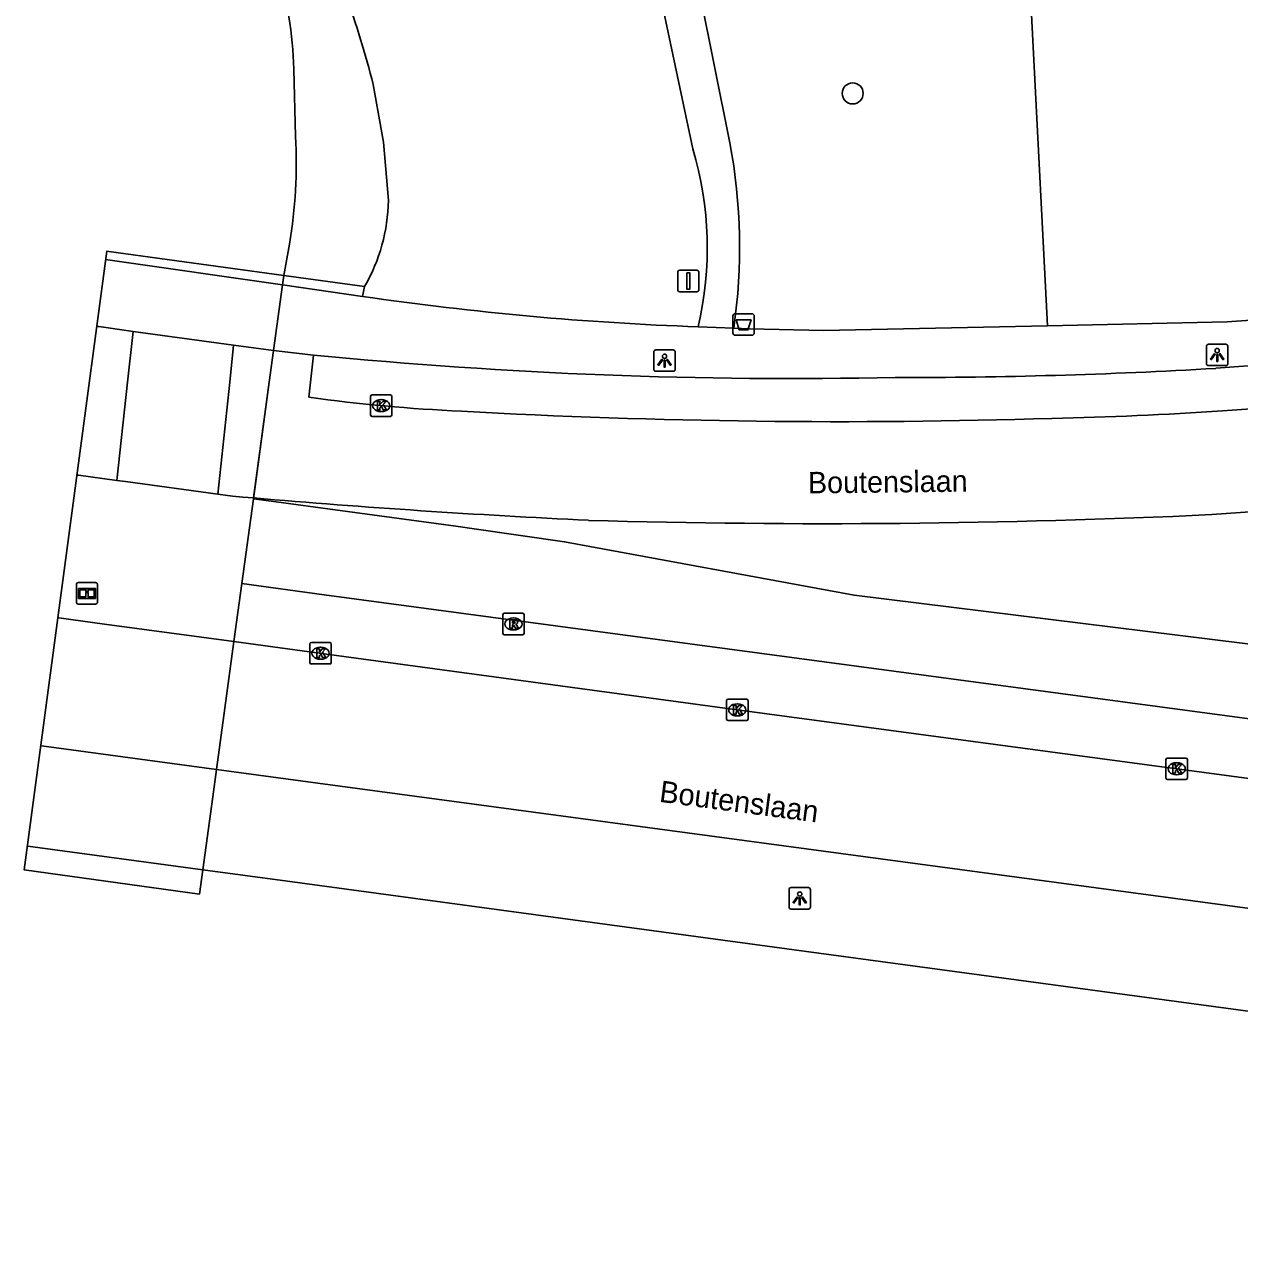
# Model space of a CAD drawing. Extents: x 161141 to 161601, y 381708 to 382245.
# Drawn here: x 161258.8 to 161315.4, y 381710.1 to 381766.7 of the extents above; entities that cross this region are included whole.
import ezdxf

# ---------------------------------------------------------------- set-up
doc = ezdxf.new("R2010")
doc.units = 0
for name, color, linetype in [('IMGEO_Afvalbak', 7, 'Continuous'), ('IMGEO_Berm_groen', 7, 'Continuous'), ('IMGEO_Boom', 7, 'Continuous'), ('IMGEO_Dek', 7, 'Continuous'), ('IMGEO_Informatiebord', 7, 'Continuous'), ('IMGEO_Kolk', 7, 'Continuous'), ('IMGEO_Lichtpunt', 7, 'Continuous'), ('IMGEO_Loofbos', 7, 'Continuous'), ('IMGEO_Muur', 7, 'Continuous'), ('IMGEO_Openbare_ruimte_label', 7, 'Continuous'), ('IMGEO_Rijbaan_lokaal_open', 7, 'Continuous'), ('IMGEO_Rijbaan_regionaal_gesloten', 7, 'Continuous'), ('IMGEO_Rioolput', 7, 'Continuous'), ('IMGEO_Verkeersbordpaal', 7, 'Continuous'), ('IMGEO_Voetpad_halfverhard', 7, 'Continuous'), ('IMGEO_Voetpad_open', 7, 'Continuous'), ('IMGEO_Waterloop', 7, 'Continuous')]:
    doc.layers.add(name, color=color, linetype=linetype)

msp = doc.modelspace()

# ---------------------------------------------------------------- linework, layer by layer
at = {"layer": 'IMGEO_Afvalbak'}
for p, q in [((161291.928, 381753.192), (161292.718, 381753.192)), ((161292.718, 381753.192), (161291.928, 381753.192)), ((161291.828, 381752.292), (161291.828, 381753.092)), ((161291.828, 381753.092), (161291.828, 381752.292)), ((161292.818, 381753.092), (161292.818, 381752.292)), ((161292.818, 381752.292), (161292.818, 381753.092)), ((161292.718, 381752.192), (161291.928, 381752.192)), ((161291.928, 381752.192), (161292.718, 381752.192))]:
    msp.add_line(p, q, dxfattribs=at)
msp.add_lwpolyline([(161291.971, 381752.906), (161292.675, 381752.906), (161292.526, 381752.436), (161292.12, 381752.436), (161291.971, 381752.906)], dxfattribs=at)
for centre, start, end in [((161291.928, 381753.092), 90, 180), ((161291.928, 381753.092), 90, 180), ((161292.718, 381753.092), 0, 90), ((161292.718, 381753.092), 360, 90), ((161291.928, 381752.292), 180, 270), ((161291.928, 381752.292), 180, 270), ((161292.718, 381752.292), 270, 0), ((161292.718, 381752.292), 270, 0)]:
    msp.add_arc(centre, 0.1, start, end, dxfattribs=at)
at = {"layer": 'IMGEO_Berm_groen'}
for points in [[(161397.032, 381723.44), (161397.056, 381723.621), (161396.92, 381724.62), (161396.612, 381725.505), (161395.912, 381726.127), (161393.777, 381727.484), (161392.598, 381727.943), (161386.682, 381728.916), (161372.991, 381730.97), (161355.514, 381733.064), (161324.679, 381736.724), (161297.467, 381740.089), (161283.989, 381742.578), (161279.785, 381743.184), (161278.93, 381743.302), (161273.313, 381744.063), (161270.564, 381744.435), (161269.503, 381744.577)], [(161268.964, 381740.632), (161272.807, 381740.117), (161390.902, 381724.29), (161397.032, 381723.44)]]:
    msp.add_lwpolyline(points, dxfattribs=at)
at = {"layer": 'IMGEO_Boom'}
msp.add_circle((161297.402, 381763.444), 0.489, dxfattribs=at)
at = {"layer": 'IMGEO_Dek'}
msp.add_lwpolyline([(161266.992, 381726.19), (161267.146, 381727.315), (161267.61, 381730.715), (161267.783, 381731.983), (161268.174, 381734.839), (161268.596, 381737.935), (161268.964, 381740.632), (161269.503, 381744.577), (161270.244, 381750), (161270.446, 381751.48), (161270.863, 381754.533), (161270.924, 381754.975), (161262.781, 381756.092), (161262.685, 381756.105), (161258.842, 381727.311)], close=True, dxfattribs=at)
at = {"layer": 'IMGEO_Informatiebord'}
for p, q in [((161261.264, 381739.778), (161261.264, 381740.578)), ((161261.264, 381740.578), (161261.264, 381739.778)), ((161261.364, 381740.678), (161262.154, 381740.678)), ((161262.154, 381740.678), (161261.364, 381740.678)), ((161262.254, 381740.578), (161262.254, 381739.778)), ((161262.254, 381739.778), (161262.254, 381740.578)), ((161262.154, 381739.678), (161261.364, 381739.678)), ((161261.364, 381739.678), (161262.154, 381739.678))]:
    msp.add_line(p, q, dxfattribs=at)
for points in [[(161261.365, 381740.41), (161262.153, 381740.41), (161262.153, 381739.946), (161261.365, 381739.946), (161261.365, 381740.41)], [(161261.43, 381740.345), (161261.43, 381740.011), (161261.705, 381740.011), (161261.706, 381740.224), (161261.81, 381740.225), (161261.811, 381740.011), (161262.088, 381740.011), (161262.088, 381740.345), (161261.812, 381740.345), (161261.812, 381740.265), (161261.706, 381740.265), (161261.706, 381740.345), (161261.43, 381740.345)]]:
    msp.add_lwpolyline(points, dxfattribs=at)
for centre, start, end in [((161261.364, 381740.578), 90, 180), ((161261.364, 381740.578), 90, 180), ((161262.154, 381740.578), 0, 90), ((161262.154, 381740.578), 360, 90), ((161261.364, 381739.778), 180, 270), ((161261.364, 381739.778), 180, 270), ((161262.154, 381739.778), 270, 0), ((161262.154, 381739.778), 270, 0)]:
    msp.add_arc(centre, 0.1, start, end, dxfattribs=at)
at = {"layer": 'IMGEO_Kolk'}
for p, q in [((161274.954, 381748.489), (161274.954, 381749.341)), ((161275.029, 381749.415), (161275.881, 381749.415)), ((161275.955, 381749.341), (161275.955, 381748.489)), ((161275.442, 381749.195), (161275.467, 381749.195)), ((161275.881, 381748.415), (161275.029, 381748.415)), ((161275.465, 381748.635), (161275.44, 381748.635)), ((161272.131, 381736.967), (161272.131, 381737.819)), ((161272.206, 381737.893), (161273.058, 381737.893)), ((161272.619, 381737.673), (161272.644, 381737.673)), ((161273.132, 381737.819), (161273.132, 381736.967)), ((161273.058, 381736.893), (161272.206, 381736.893)), ((161272.642, 381737.113), (161272.617, 381737.113)), ((161291.53, 381734.332), (161291.53, 381735.184)), ((161291.605, 381735.258), (161292.457, 381735.258)), ((161292.531, 381735.184), (161292.531, 381734.332)), ((161292.018, 381735.038), (161292.043, 381735.038)), ((161292.457, 381734.258), (161291.605, 381734.258)), ((161292.041, 381734.478), (161292.016, 381734.478)), ((161311.983, 381731.591), (161311.983, 381732.443)), ((161312.058, 381732.517), (161312.91, 381732.517)), ((161312.471, 381732.297), (161312.496, 381732.297)), ((161312.984, 381732.443), (161312.984, 381731.591)), ((161312.494, 381731.737), (161312.469, 381731.737)), ((161312.91, 381731.517), (161312.058, 381731.517))]:
    msp.add_line(p, q, dxfattribs=at)
for points in [[(161274.954, 381748.489), (161274.954, 381749.341)], [(161275.029, 381749.415), (161275.881, 381749.415)], [(161275.955, 381749.341), (161275.955, 381748.489)], [(161275.275, 381749.115), (161275.398, 381749.115), (161275.398, 381748.964), (161275.528, 381749.115), (161275.692, 381749.115), (161275.546, 381748.964), (161275.699, 381748.715), (161275.547, 381748.715), (161275.462, 381748.879), (161275.398, 381748.812), (161275.398, 381748.715), (161275.275, 381748.715), (161275.275, 381749.115)], [(161275.881, 381748.415), (161275.029, 381748.415)], [(161272.131, 381736.967), (161272.131, 381737.819)], [(161272.206, 381737.893), (161273.058, 381737.893)], [(161272.452, 381737.593), (161272.575, 381737.593), (161272.575, 381737.442), (161272.705, 381737.593), (161272.869, 381737.593), (161272.723, 381737.442), (161272.876, 381737.193), (161272.724, 381737.193), (161272.639, 381737.357), (161272.575, 381737.29), (161272.575, 381737.193), (161272.452, 381737.193), (161272.452, 381737.593)], [(161273.132, 381737.819), (161273.132, 381736.967)], [(161273.058, 381736.893), (161272.206, 381736.893)], [(161291.53, 381734.332), (161291.53, 381735.184)], [(161291.605, 381735.258), (161292.457, 381735.258)], [(161292.531, 381735.184), (161292.531, 381734.332)], [(161291.851, 381734.958), (161291.974, 381734.958), (161291.974, 381734.807), (161292.104, 381734.958), (161292.268, 381734.958), (161292.122, 381734.807), (161292.275, 381734.558), (161292.123, 381734.558), (161292.038, 381734.722), (161291.974, 381734.655), (161291.974, 381734.558), (161291.851, 381734.558), (161291.851, 381734.958)], [(161292.457, 381734.258), (161291.605, 381734.258)], [(161311.983, 381731.591), (161311.983, 381732.443)], [(161312.058, 381732.517), (161312.91, 381732.517)], [(161312.984, 381732.443), (161312.984, 381731.591)], [(161312.304, 381732.217), (161312.427, 381732.217), (161312.427, 381732.066), (161312.557, 381732.217), (161312.721, 381732.217), (161312.575, 381732.066), (161312.728, 381731.817), (161312.576, 381731.817), (161312.491, 381731.981), (161312.427, 381731.914), (161312.427, 381731.817), (161312.304, 381731.817), (161312.304, 381732.217)], [(161312.91, 381731.517), (161312.058, 381731.517)]]:
    msp.add_lwpolyline(points, dxfattribs=at)
for centre, start, end in [((161275.031, 381749.339), 91.552, 178.448), ((161275.031, 381749.339), 91.552, 178.448), ((161275.879, 381749.339), 1.552, 88.448), ((161275.879, 381749.339), 1.552, 88.448), ((161275.031, 381748.491), 181.552, 268.448), ((161275.031, 381748.491), 181.552, 268.448), ((161275.879, 381748.491), 271.552, 358.448), ((161275.879, 381748.491), 271.552, 358.448), ((161272.208, 381737.817), 91.552, 178.448), ((161272.208, 381737.817), 91.552, 178.448), ((161273.056, 381737.817), 1.552, 88.448), ((161273.056, 381737.817), 1.552, 88.448), ((161272.208, 381736.969), 181.552, 268.448), ((161272.208, 381736.969), 181.552, 268.448), ((161273.056, 381736.969), 271.552, 358.448), ((161273.056, 381736.969), 271.552, 358.448), ((161291.607, 381735.182), 91.552, 178.448), ((161291.607, 381735.182), 91.552, 178.448), ((161292.455, 381735.182), 1.552, 88.448), ((161292.455, 381735.182), 1.552, 88.448), ((161291.607, 381734.334), 181.552, 268.448), ((161291.607, 381734.334), 181.552, 268.448), ((161292.455, 381734.334), 271.552, 358.448), ((161292.455, 381734.334), 271.552, 358.448), ((161312.06, 381732.441), 91.552, 178.448), ((161312.06, 381732.441), 91.552, 178.448), ((161312.908, 381732.441), 1.552, 88.448), ((161312.908, 381732.441), 1.552, 88.448), ((161312.06, 381731.593), 181.552, 268.448), ((161312.06, 381731.593), 181.552, 268.448), ((161312.908, 381731.593), 271.552, 358.448), ((161312.908, 381731.593), 271.552, 358.448)]:
    msp.add_arc(centre, 0.0765, start, end, dxfattribs=at)
for centre, major_axis, ratio, start_param, end_param in [((161275.441, 381748.915), (-0.387, 0.002), 0.722429, 4.712389, 7.853982), ((161275.466, 381748.915), (-0.39, 0.002), 0.717154, 1.570796, 4.712389), ((161272.618, 381737.393), (-0.387, 0.002), 0.722429, 4.712389, 7.853982), ((161272.643, 381737.393), (-0.39, 0.002), 0.717154, 1.570796, 4.712389), ((161292.017, 381734.758), (-0.387, 0.002), 0.722429, 4.712389, 7.853982), ((161292.042, 381734.758), (-0.39, 0.002), 0.717154, 1.570796, 4.712389), ((161312.47, 381732.017), (-0.387, 0.002), 0.722429, 4.712389, 7.853982), ((161312.495, 381732.017), (-0.39, 0.002), 0.717154, 1.570796, 4.712389)]:
    msp.add_ellipse(centre, major_axis=major_axis, ratio=ratio, start_param=start_param, end_param=end_param, dxfattribs=at)
at = {"layer": 'IMGEO_Lichtpunt'}
for p, q in [((161289.046, 381751.508), (161288.238, 381751.508)), ((161289.046, 381751.508), (161288.238, 381751.508)), ((161313.869, 381751.677), (161313.869, 381750.87)), ((161313.869, 381751.677), (161313.869, 381750.87)), ((161314.771, 381751.772), (161313.963, 381751.772)), ((161314.771, 381751.772), (161313.963, 381751.772)), ((161314.865, 381750.87), (161314.865, 381751.677)), ((161314.865, 381750.87), (161314.865, 381751.677)), ((161288.144, 381751.413), (161288.144, 381750.606)), ((161288.144, 381751.413), (161288.144, 381750.606)), ((161289.14, 381750.606), (161289.14, 381751.413)), ((161289.14, 381750.606), (161289.14, 381751.413)), ((161288.238, 381750.512), (161289.046, 381750.512)), ((161288.238, 381750.512), (161289.046, 381750.512)), ((161313.963, 381750.776), (161314.771, 381750.776)), ((161313.963, 381750.776), (161314.771, 381750.776)), ((161294.439, 381726.392), (161294.439, 381725.585)), ((161294.439, 381726.392), (161294.439, 381725.585)), ((161295.341, 381726.487), (161294.533, 381726.487)), ((161295.341, 381726.487), (161294.533, 381726.487)), ((161295.435, 381725.585), (161295.435, 381726.392)), ((161295.435, 381725.585), (161295.435, 381726.392)), ((161294.533, 381725.491), (161295.341, 381725.491)), ((161294.533, 381725.491), (161295.341, 381725.491))]:
    msp.add_line(p, q, dxfattribs=at)
for points in [[(161288.518, 381751.077), (161288.557, 381751.049), (161288.369, 381750.787), (161288.331, 381750.814), (161288.518, 381751.077)], [(161288.62, 381751.029), (161288.667, 381751.029), (161288.667, 381750.707), (161288.62, 381750.707), (161288.62, 381751.029)], [(161288.73, 381751.049), (161288.768, 381751.076), (161288.955, 381750.814), (161288.916, 381750.786), (161288.73, 381751.049)], [(161314.243, 381751.341), (161314.282, 381751.313), (161314.094, 381751.051), (161314.056, 381751.078), (161314.243, 381751.341)], [(161314.345, 381751.293), (161314.392, 381751.293), (161314.392, 381750.971), (161314.345, 381750.971), (161314.345, 381751.293)], [(161314.455, 381751.313), (161314.493, 381751.34), (161314.68, 381751.078), (161314.641, 381751.05), (161314.455, 381751.313)], [(161294.813, 381726.056), (161294.852, 381726.028), (161294.664, 381725.766), (161294.626, 381725.793), (161294.813, 381726.056)], [(161295.025, 381726.028), (161295.063, 381726.055), (161295.25, 381725.793), (161295.211, 381725.765), (161295.025, 381726.028)], [(161294.915, 381726.008), (161294.962, 381726.008), (161294.962, 381725.686), (161294.915, 381725.686), (161294.915, 381726.008)]]:
    msp.add_lwpolyline(points, dxfattribs=at)
for centre in [(161314.368, 381751.475), (161288.643, 381751.211), (161294.938, 381726.19)]:
    msp.add_circle(centre, 0.0994, dxfattribs=at)
for centre, start, end in [((161288.238, 381751.413), 90, 180), ((161288.238, 381751.413), 90, 180), ((161289.046, 381751.413), 0, 90), ((161289.046, 381751.413), 0, 90), ((161313.963, 381751.677), 90, 180), ((161313.963, 381751.677), 90, 180), ((161314.771, 381751.677), 0, 90), ((161314.771, 381751.677), 0, 90), ((161288.238, 381750.606), 180, 270), ((161288.238, 381750.606), 180, 270), ((161289.046, 381750.606), 270, 0), ((161289.046, 381750.606), 270, 360), ((161313.963, 381750.87), 180, 270), ((161313.963, 381750.87), 180, 270), ((161314.771, 381750.87), 270, 0), ((161314.771, 381750.87), 270, 360), ((161294.533, 381726.392), 90, 180), ((161294.533, 381726.392), 90, 180), ((161295.341, 381726.392), 0, 90), ((161295.341, 381726.392), 0, 90), ((161294.533, 381725.585), 180, 270), ((161294.533, 381725.585), 180, 270), ((161295.341, 381725.585), 270, 0), ((161295.341, 381725.585), 270, 360)]:
    msp.add_arc(centre, 0.0946, start, end, dxfattribs=at)
at = {"layer": 'IMGEO_Loofbos'}
for points in [[(161306.475, 381752.633), (161304.865, 381783.723)], [(161275.788, 381758.457), (161275.561, 381761.176), (161275.087, 381763.862)]]:
    msp.add_lwpolyline(points, dxfattribs=at)
for centre, radius, start, end in [((161225.5, 381750.991), 51.23, 14.5512, 24.2931), ((161267.538, 381758.589), 8.251, 329.9766, 359.0817)]:
    msp.add_arc(centre, radius, start, end, dxfattribs=at)
at = {"layer": 'IMGEO_Muur'}
for points in [[(161270.863, 381754.533), (161262.727, 381755.697), (161262.632, 381755.711)], [(161270.863, 381754.533), (161270.924, 381754.975)], [(161270.924, 381754.975), (161274.682, 381754.461)], [(161274.587, 381754), (161270.863, 381754.533)], [(161274.682, 381754.461), (161274.587, 381754)]]:
    msp.add_lwpolyline(points, dxfattribs=at)
at = {"layer": 'IMGEO_Rijbaan_lokaal_open'}
for points in [[(161262.217, 381752.605), (161262.303, 381752.593), (161262.639, 381752.544), (161263.907, 381752.371)], [(161263.146, 381745.438), (161263.647, 381750), (161263.907, 381752.371)], [(161263.907, 381752.371), (161268.584, 381751.734)], [(161268.584, 381751.734), (161268.402, 381750), (161267.855, 381744.799)], [(161268.584, 381751.734), (161270.446, 381751.48)], [(161269.509, 381744.62), (161270.244, 381750), (161270.446, 381751.48)], [(161269.509, 381744.62), (161270.244, 381750), (161270.446, 381751.48)], [(161272.307, 381751.27), (161270.446, 381751.48)], [(161272.307, 381751.27), (161272.086, 381749.309)], [(161314.611, 381748.68), (161328.834, 381749.672)], [(161263.146, 381745.438), (161261.357, 381745.672), (161261.293, 381745.681)], [(161267.855, 381744.799), (161263.559, 381745.382), (161263.146, 381745.438)], [(161269.509, 381744.62), (161269.019, 381744.662), (161268.53, 381744.705), (161267.855, 381744.799)], [(161314.112, 381743.844), (161329.226, 381744.898)]]:
    msp.add_lwpolyline(points, dxfattribs=at)
for centre, radius, start, end in [((161282.514, 381823.873), 75.289, 262.03887, 267.46603), ((161303.629, 381903.982), 155.69, 271.12049, 274.04469), ((161296.792, 382065.432), 317.264, 266.81866, 271.78491), ((161305.423, 382165.044), 421.955, 265.11741, 267.24079), ((161296.089, 382127.744), 384.323, 268.36314, 272.68788)]:
    msp.add_arc(centre, radius, start, end, dxfattribs=at)
at = {"layer": 'IMGEO_Rijbaan_regionaal_gesloten'}
for points in [[(161260.408, 381739.045), (161260.451, 381739.039), (161262.58, 381738.75), (161268.596, 381737.935)], [(161267.783, 381731.983), (161268.174, 381734.839), (161268.596, 381737.935)], [(161268.596, 381737.935), (161272.46, 381737.411), (161292.031, 381734.758), (161396.904, 381720.692)], [(161267.783, 381731.983), (161259.637, 381733.078), (161259.612, 381733.081)], [(161396.075, 381714.735), (161271.697, 381731.457), (161267.783, 381731.983)], [(161258.99, 381728.417), (161259, 381728.416), (161267.146, 381727.315)], [(161266.992, 381726.19), (161267.146, 381727.315)], [(161395.417, 381710.059), (161388.748, 381710.952), (161341.985, 381717.206), (161295.256, 381723.516), (161271.097, 381726.781), (161267.146, 381727.315)]]:
    msp.add_lwpolyline(points, dxfattribs=at)
at = {"layer": 'IMGEO_Rioolput'}
for p, q in [((161281.11, 381738.33), (161281.11, 381739.182)), ((161281.185, 381739.256), (161282.037, 381739.256)), ((161282.111, 381739.182), (161282.111, 381738.33)), ((161281.621, 381738.476), (161281.596, 381738.476)), ((161281.598, 381739.036), (161281.623, 381739.036)), ((161282.037, 381738.256), (161281.185, 381738.256))]:
    msp.add_line(p, q, dxfattribs=at)
for points in [[(161281.11, 381738.33), (161281.11, 381739.182)], [(161281.185, 381739.256), (161282.037, 381739.256)], [(161282.111, 381739.182), (161282.111, 381738.33)], [(161281.699, 381738.954), (161281.447, 381738.956), (161281.447, 381738.556)], [(161281.447, 381738.556), (161281.571, 381738.556), (161281.571, 381738.718), (161281.582, 381738.718)], [(161281.625, 381738.875), (161281.571, 381738.875), (161281.571, 381738.794)], [(161281.571, 381738.794), (161281.623, 381738.794)], [(161281.629, 381738.689), (161281.7, 381738.556), (161281.84, 381738.556), (161281.775, 381738.682)], [(161282.037, 381738.256), (161281.185, 381738.256)]]:
    msp.add_lwpolyline(points, dxfattribs=at)
for centre, radius, start, end in [((161281.187, 381739.18), 0.0765, 91.552, 178.448), ((161281.187, 381739.18), 0.0765, 91.552, 178.448), ((161282.035, 381739.18), 0.0765, 1.552, 88.448), ((161282.035, 381739.18), 0.0765, 1.552, 88.448), ((161281.581, 381738.665), 0.0533, 26.0293, 88.6989), ((161281.607, 381738.983), 0.19, 274.7715, 282.9687), ((161281.631, 381738.779), 0.0964, 77.0061, 93.1865), ((161281.645, 381738.836), 0.0378, 276.6634, 79.6772), ((161281.698, 381738.844), 0.109, 350.3612, 89.416), ((161281.696, 381738.844), 0.112, 277.5842, 350.9817), ((161281.68, 381738.629), 0.108, 29.5134, 73.7905), ((161281.187, 381738.332), 0.0765, 181.552, 268.448), ((161281.187, 381738.332), 0.0765, 181.552, 268.448), ((161282.035, 381738.332), 0.0765, 271.552, 358.448), ((161282.035, 381738.332), 0.0765, 271.552, 358.448)]:
    msp.add_arc(centre, radius, start, end, dxfattribs=at)
for centre, major_axis, ratio, start_param, end_param in [((161281.597, 381738.756), (-0.387, 0.002), 0.722429, 4.712389, 7.853982), ((161281.622, 381738.756), (-0.39, 0.002), 0.717154, 1.570796, 4.712389)]:
    msp.add_ellipse(centre, major_axis=major_axis, ratio=ratio, start_param=start_param, end_param=end_param, dxfattribs=at)
at = {"layer": 'IMGEO_Verkeersbordpaal'}
for p, q in [((161289.255, 381754.317), (161289.255, 381755.117)), ((161289.255, 381755.117), (161289.255, 381754.317)), ((161289.355, 381755.217), (161290.145, 381755.217)), ((161290.145, 381755.217), (161289.355, 381755.217)), ((161290.245, 381755.117), (161290.245, 381754.317)), ((161290.245, 381754.317), (161290.245, 381755.117)), ((161290.145, 381754.217), (161289.355, 381754.217)), ((161289.355, 381754.217), (161290.145, 381754.217))]:
    msp.add_line(p, q, dxfattribs=at)
msp.add_lwpolyline([(161289.675, 381755.092), (161289.825, 381755.092), (161289.825, 381754.342), (161289.675, 381754.342), (161289.675, 381755.092)], dxfattribs=at)
for centre, start, end in [((161289.355, 381755.117), 90, 180), ((161289.355, 381755.117), 90, 180), ((161290.145, 381755.117), 0, 90), ((161290.145, 381755.117), 360, 90), ((161289.355, 381754.317), 180, 270), ((161289.355, 381754.317), 180, 270), ((161290.145, 381754.317), 270, 0), ((161290.145, 381754.317), 270, 0)]:
    msp.add_arc(centre, 0.1, start, end, dxfattribs=at)
at = {"layer": 'IMGEO_Voetpad_halfverhard'}
for points in [[(161291.688, 381761.143), (161288.144, 381778.757), (161286.746, 381788.059), (161286.601, 381788.716), (161286.633, 381789.053), (161286.838, 381789.358), (161287.164, 381789.416), (161288.077, 381789.228), (161303.519, 381784.165), (161304.865, 381783.723)], [(161286.239, 381778.44), (161289.964, 381760.867)]]:
    msp.add_lwpolyline(points, dxfattribs=at)
for centre, radius, start, end in [((161265.545, 381756.284), 26.59, 351.8484, 10.5284), ((161274.372, 381756.253), 16.26, 346.9593, 16.4844)]:
    msp.add_arc(centre, radius, start, end, dxfattribs=at)
at = {"layer": 'IMGEO_Voetpad_open'}
for points in [[(161306.475, 381752.633), (161314.828, 381752.814), (161371.777, 381756.831)], [(161398.537, 381754.559), (161398.422, 381756.585), (161322.892, 381751.276), (161314.304, 381750.651)], [(161270.446, 381751.48), (161270.863, 381754.533)], [(161291.867, 381752.514), (161292.229, 381752.501), (161292.592, 381752.488), (161296.045, 381752.406), (161306.475, 381752.633)], [(161290.213, 381752.584), (161291.04, 381752.549), (161291.867, 381752.514)]]:
    msp.add_lwpolyline(points, dxfattribs=at)
for centre, radius, start, end in [((161295.257, 381895.174), 142.679, 261.67018, 267.97403), ((161294.664, 381979.244), 229.068, 264.39906, 271.18047), ((161299.796, 381997.265), 247.041, 269.9041, 273.36664)]:
    msp.add_arc(centre, radius, start, end, dxfattribs=at)
at = {"layer": 'IMGEO_Waterloop'}
for points in [[(161271.467, 381761.446), (161271.381, 381764.575)], [(161270.924, 381754.975), (161271.183, 381756.434)], [(161268.964, 381740.632), (161269.503, 381744.577)], [(161269.503, 381744.577), (161269.509, 381744.62)], [(161268.596, 381737.935), (161268.964, 381740.632)], [(161267.146, 381727.315), (161267.61, 381730.715), (161267.783, 381731.983)]]:
    msp.add_lwpolyline(points, dxfattribs=at)
for centre, radius, start, end in [((161254.431, 381764.232), 16.954, 1.1589, 17.6768), ((161248.476, 381760.235), 23.023, 350.4979, 3.0158)]:
    msp.add_arc(centre, radius, start, end, dxfattribs=at)

# ---------------------------------------------------------------- texts
at = {"layer": 'IMGEO_Openbare_ruimte_label'}
for rotation, p in [(0.6302, (161295.323, 381744.831)), (352.5266, (161288.366, 381730.483))]:
    msp.add_text('Boutenslaan', height=1, rotation=rotation, dxfattribs=at).set_placement(p)

doc.saveas('drawing.dxf')
